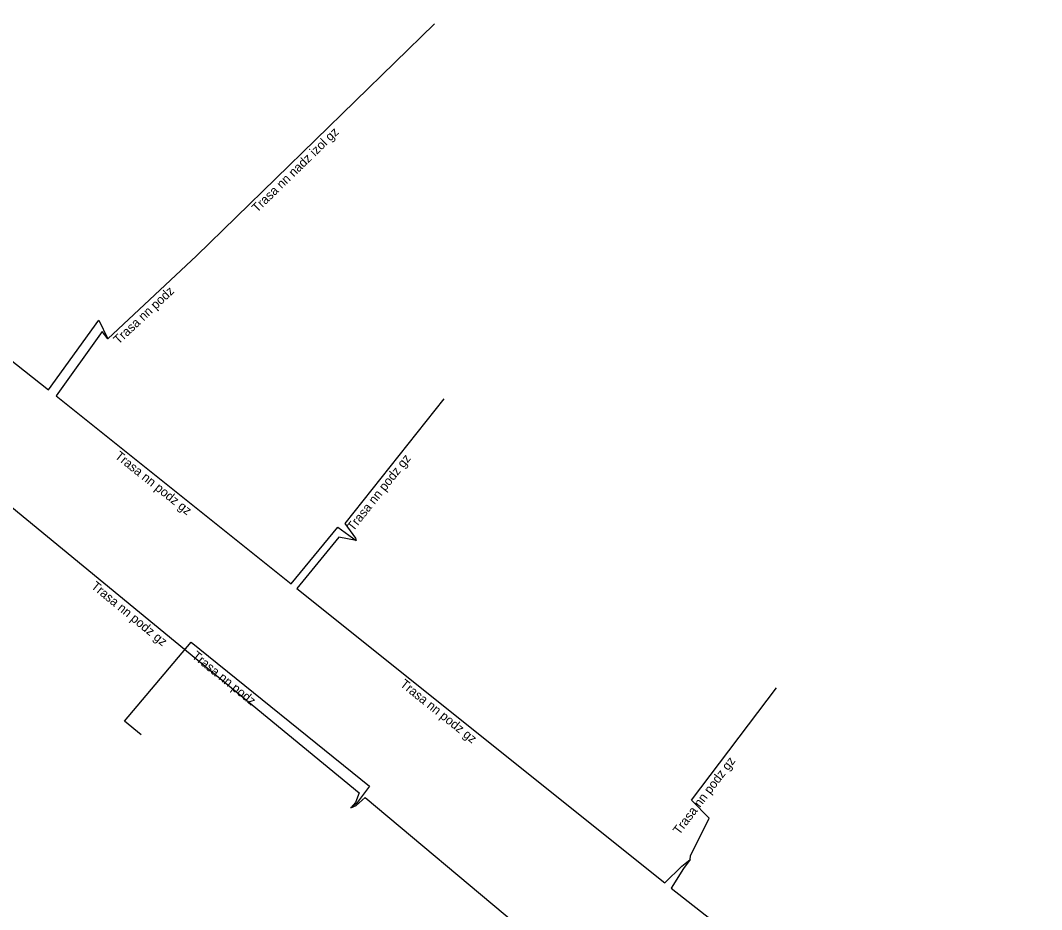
# Model space of a CAD drawing. Extents: x -484846 to -484244, y -1128177 to -1127608.
# Drawn here: x -484426.4 to -484370, y -1128092.2 to -1128043.1 of the extents above; entities that cross this region are included whole.
import ezdxf

# ---------------------------------------------------------------- set-up
doc = ezdxf.new("R2010")
doc.units = 0
doc.layers.add('Popiskový text - Ostatní atributy Trasy', color=7, linetype='Continuous')
doc.layers.add('Spojnice NN', color=7, linetype='Continuous')

msp = doc.modelspace()

# ---------------------------------------------------------------- linework, layer by layer
at = {"layer": 'Spojnice NN'}
for points in [[(-484436.189, -1128043.101), (-484436.483, -1128043.799), (-484437.004, -1128045.358), (-484440.712, -1128050.969), (-484424.85, -1128063.514), (-484422.078, -1128059.675), (-484421.58, -1128060.7)], [(-484403.508, -1128043.289), (-484416.68, -1128056.11)], [(-484421.58, -1128060.7), (-484416.68, -1128056.11)], [(-484421.58, -1128060.7), (-484421.89, -1128060.3), (-484424.432, -1128063.856), (-484411.434, -1128074.233), (-484408.864, -1128071.113), (-484407.854, -1128071.84)], [(-484403.007, -1128064.019), (-484408.481, -1128070.912), (-484407.881, -1128071.715), (-484407.854, -1128071.84)], [(-484430.181, -1128072.191), (-484430.51, -1128071.81), (-484428.05, -1128069.07), (-484407.69, -1128085.784), (-484407.884, -1128086.329), (-484408.15, -1128086.611)], [(-484407.854, -1128071.84), (-484408.801, -1128071.664), (-484411.126, -1128074.487), (-484390.79, -1128090.77), (-484389.841, -1128089.849), (-484389.376, -1128089.475)], [(-484419.73, -1128082.591), (-484420.65, -1128081.822), (-484416.967, -1128077.459), (-484407.115, -1128085.427), (-484407.82, -1128086.387), (-484408.15, -1128086.611)], [(-484389.376, -1128089.475), (-484389.362, -1128089.278), (-484388.34, -1128087.18), (-484389.312, -1128086.186), (-484384.604, -1128079.992)], [(-484408.15, -1128086.611), (-484407.856, -1128086.495), (-484407.348, -1128086.049), (-484399.049, -1128093.015), (-484393.9, -1128097.12), (-484388.59, -1128101.75), (-484388.3, -1128102.76), (-484387.45, -1128103.34), (-484386.09, -1128103.38), (-484385.646, -1128103.837), (-484381.711, -1128098.968), (-484378.29, -1128101.266), (-484374.927, -1128103.786), (-484371.042, -1128107.194), (-484369.96, -1128107.41)], [(-484389.376, -1128089.475), (-484389.761, -1128089.964), (-484390.436, -1128091.049), (-484383.26, -1128096.67), (-484381.08, -1128098.89), (-484377.99, -1128100.81), (-484374.67, -1128103.48), (-484370.742, -1128106.853), (-484369.96, -1128107.41)]]:
    msp.add_lwpolyline(points, dxfattribs=at)

# ---------------------------------------------------------------- texts
at = {"layer": 'Popiskový text - Ostatní atributy Trasy'}
for s, rotation, p in [('Trasa nn nadz izol gz', 44.2269, (-484413.321, -1128053.747)), ('Trasa nn podz', 43.129, (-484420.983, -1128061.031)), ('Trasa nn podz gz', 321.3978, (-484421.222, -1128067.251)), ('Trasa nn podz gz', 51.5455, (-484408.008, -1128071.362)), ('Trasa nn podz gz', 320.6166, (-484422.536, -1128074.438)), ('Trasa nn podz', 321.0351, (-484416.965, -1128078.297)), ('Trasa nn podz gz', 321.3158, (-484405.459, -1128079.857)), ('Trasa nn podz gz', 52.7619, (-484389.983, -1128088.143))]:
    msp.add_text(s, height=0.5, rotation=rotation, dxfattribs=at).set_placement(p)

doc.saveas('drawing.dxf')
